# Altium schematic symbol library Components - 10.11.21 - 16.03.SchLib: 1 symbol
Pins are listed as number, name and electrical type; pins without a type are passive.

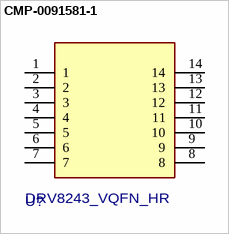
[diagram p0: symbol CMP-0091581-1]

## CMP-0091581-1
designator U?, comment DRV8243_VQFN_HR
Manufacturer: Texas Instruments; Standoff Height: 0mm; SizeZ_mm: 1mm
footprint RXY0014A-MFG
pins: 1, 2, 3, 4, 5, 6, 7, 8, 9, 10, 11, 12, 13, 14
